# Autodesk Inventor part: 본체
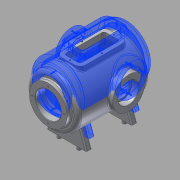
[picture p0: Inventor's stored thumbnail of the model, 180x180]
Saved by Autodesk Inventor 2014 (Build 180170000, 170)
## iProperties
Created: 2016-02
Part Number: 본체
Material: 알루미늄 6061
Document SubType Name: Modeling
Designer: mduedu
Density: 2.71 g/cm^3
Appearance: 알루미늄 - 평지
Mass: 2843.95 g
Surface Area: 2031.13 cm^2
Volume: 1049.43 cm^3
Author: mduedu
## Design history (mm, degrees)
sketch "스케치2"
  geometry: L1 (0, 100)-(0, -100); L2 (65, -75.993)-(65, 100); L3 (65, 100)-(0, 100); A1 r 100 centre (0, 0) between (0, -100) and (65, -75.993); 2 further points
  constraints: 6 end point, 2 midpoint, 2 point on circle, 1 centre point, 1 coincident, 1 horizontal, 1 parallel, 1 vertical
  dimensions: "d3" = 200 distance of L1.start L1.end; "d5" = 130 diameter of L2 L1; "d6" = 100 radius of A1
revolve "회전1" sketch "스케치2" stored, may be unused: angle "d7" = 90 deg
sketch "스케치3"
  geometry: C1 r 47.5 at (0, 0); 1 further point
  constraints: 1 centre point, 1 coincident
  dimensions: "d8" = 95 diameter of C1
extrude "돌출2" join sketch "스케치3" distance "d10" = 10; taper "d11" = 0 deg
sketch "스케치5"
  geometry: L1 (47.5, 110)-(47.5, 100) reference; L2 (47.5, 100)-(65, 100) reference; L3 (65, 100)-(65, -75.993) reference; L4 (-65, -75.993)-(-65, 100) reference; L5 (-65, 100)-(-47.5, 100) reference; L6 (-47.5, 100)-(-47.5, 110) reference; L7 (-47.5, 110)-(47.5, 110) reference; L8 (55, 85)-(55, -71.239); L9 (0, 85)-(55, 85); L10 (0, 85)-(0, -90); A1 r 100 centre (0, 0) between (0, -100) and (65, -75.993) reference; A2 r 100 centre (0, 0) between (-65, -75.993) and (0, -100) reference; A3 r 90 centre (0, 0) between (0, -90) and (55, -71.239); 1 further point
  constraints: 6 end point, 2 point on circle, 1 centre point, 1 parallel, 1 perpendicular, 1 point on line, 1 vertical
  dimensions: "d13" = 10 distance between parallel lines of L3 L8; "d14" = 10 radial gap between concentric circles of A3 A1; "d15" = 15 distance between parallel lines of L9 L2
revolve "회전2" sketch "스케치5" stored, may be unused: angle "d16" = 90 deg
hole "구멍1" diameter "d19" = 65; stored, may be unused: countersink angle "d23" = 90 deg, drill point angle "d25" = 118 deg; dims "d17" = 10, "d18" = 10, "d20" = 6, "d21" = 4, "d22" = 2, "d24" = 8
node "작업 평면1"
sketch "스케치6"
  geometry: L1 (47.5, 110)-(-47.5, 110) reference; C1 r 40 at (0, -17); 1 further point
  constraints: 1 centre point, 1 vertical alignment
  dimensions: "d27" = 80 diameter of C1; "d29" = 127 distance from line of C1.centre L1
extrude "돌출3" join sketch "스케치6" stored distance "d30" = 10; taper "d31" = 0 deg
hole "구멍2" diameter "d34" = 42; stored, may be unused: countersink angle "d38" = 90 deg, drill point angle "d40" = 118 deg; dims "d32" = 10, "d33" = 10, "d35" = 6, "d36" = 52, "d37" = 18, "d39" = 8
sketch "스케치7" dims "d41" = 65
  geometry: C1 r 40 at (0, 0) reference; 3 further points
  constraints: 2 vertical alignment, 1 coincident, 2 other
hole "구멍3" sketch "스케치7" at (0, 32.5) diameter "d43" = 3.242; stored, may be unused: countersink angle "d47" = 90 deg, drill point angle "d49" = 118 deg; dims "d44" = 11, "d45" = 13, "d46" = 18, "d48" = 13
sketch "스케치8" dims "d53" = 80
  geometry: 3 further points
  constraints: 2 vertical alignment, 1 coincident, 2 other
hole "구멍4" sketch "스케치8" at (0, 40) diameter "d56" = 3.242; stored, may be unused: countersink angle "d60" = 90 deg, drill point angle "d62" = 118 deg; dims "d57" = 11, "d58" = 13, "d59" = 18, "d61" = 13
fillet "모깎기1" dims "d66" = 10
fillet "모깎기2" dims "d67" = 3
fillet "모깎기3" dims "d68" = 0.3
chamfer "모따기1" distance "d69" = 1; stored, may be unused: second distance "d70" = 2, angle "d71" = 45 deg
node "작업 평면5"
sketch "스케치10"
  geometry: L1 (-50, -64)-(50, -64); L2 (50, -64)-(50, -50); L3 (50, -50)-(-50, -50); L4 (-50, -50)-(-50, -64); L5 (-50, 0)-(50, 0); L6 (-50, 64)-(50, 64); L7 (50, 64)-(50, 50); L8 (50, 50)-(-50, 50); L9 (-50, 50)-(-50, 64); 2 further points
  constraints: 18 end point, 4 symmetric about line, 2 parallel, 2 perpendicular, 1 coincident, 1 horizontal, 1 midpoint
  dimensions: "d80" = 14 distance of L3.end L1.start; "d82" = 100 distance of L1.start L1.end; "d130" = 50 horizontal distance of L3.end point (0, 0); "d131" = 50 horizontal distance of L3.end point (0, 0); "d132" = 100 distance of L5.start L5.end
extrude "돌출5" join sketch "스케치10" stored distance "d84" = 10; taper "d85" = 0 deg
feature "면 기울기3" dims angle "d135" = 20 deg
sketch "스케치11"
  geometry: L1 (-85, -50)-(-85, 50); L2 (-65, 90)-(-65, -71.239) reference; L3 (-100, -50)-(-41.533, -50) reference; L4 (-100, 50)-(-41.533, 50) reference; 1 further point
  constraints: 2 end point, 2 point on line
  dimensions: "d87" = 20 distance between parallel lines of L1 L2
feature "리브1" sketch "스케치11" dims "d88" = 1, "d89" = 8, "d90" = 0, "d91" = 0, "d92" = 1, "d93" = 1
fillet "모깎기5" dims "d103" = 3
fillet "모깎기6" dims "d105" = 3
node "작업 평면6"
sketch "스케치15"
  geometry: L1 (-30, 60)-(30, 60); L2 (30, 60)-(30, -60); L3 (30, -60)-(-30, -60); L4 (-30, -60)-(-30, 60); 2 further points
  constraints: 8 end point, 2 parallel, 1 horizontal, 1 midpoint, 1 perpendicular, 1 vertical alignment
  dimensions: "d110" = 60 distance of L2.end L3.end; "d112" = 60 distance from line of L3 point (0, 0); "d113" = 120 distance of L1.end L2.end
extrude "돌출8" join sketch "스케치15" stored distance "d114" = 10; taper "d115" = 0 deg
fillet "모깎기7" dims "d116" = 15
sketch "스케치16"
  geometry: L1 (-30, -45)-(-30, 45) reference; L2 (30, 45)-(30, -45) reference; L3 (-15, 60)-(15, 60) reference; L4 (15, -60)-(-15, -60) reference; L5 (-20, -45)-(-20, 45); L6 (-15, 50)-(15, 50); L7 (20, 45)-(20, -45); L8 (15, -50)-(-15, -50); A1 r 15 centre (-15, -45) between (-30, -45) and (-15, -60) reference; A2 r 15 centre (-15, 45) between (-15, 60) and (-30, 45) reference; A3 r 15 centre (15, 45) between (30, 45) and (15, 60) reference; A4 r 15 centre (15, -45) between (15, -60) and (30, -45) reference; A5 r 5 centre (-15, -45) between (-20, -45) and (-15, -50); A6 r 5 centre (-15, 45) between (-15, 50) and (-20, 45); A7 r 5 centre (15, 45) between (20, 45) and (15, 50); A8 r 5 centre (15, -45) between (15, -50) and (20, -45)
  constraints: 8 end point, 8 point on circle, 4 centre point, 7 other
  dimensions: "d137" = 10 distance between parallel lines of L5 L1
extrude "돌출9" cut sketch "스케치16" stored distance "d118" = 10; taper "d119" = 0 deg
fillet "모깎기8" dims "d120" = 3
sketch "스케치17"
  geometry: L1 (-30, -45)-(-30, 45) reference; L2 (30, 45)-(30, -45) reference; L3 (-20, 45)-(-20, -45) reference; L4 (-15, -50)-(15, -50) reference; L5 (20, -45)-(20, 45) reference; L6 (15, 50)-(-15, 50) reference; L7 (-15, 60)-(15, 60) reference; L8 (15, -60)-(-15, -60) reference; L9 (15, 55)-(-15, 55); L10 (-25, 45)-(-25, -45); L11 (-15, -55)-(15, -55); L12 (25, -45)-(25, 45); A1 r 5 centre (-15, 45) between (-15, 50) and (-20, 45) reference; A2 r 5 centre (-15, -45) between (-20, -45) and (-15, -50) reference; A3 r 5 centre (15, -45) between (15, -50) and (20, -45) reference; A4 r 5 centre (15, 45) between (20, 45) and (15, 50) reference; A5 r 15 centre (-15, 45) between (-15, 60) and (-30, 45) reference; A6 r 15 centre (15, 45) between (30, 45) and (15, 60) reference; A7 r 15 centre (15, -45) between (15, -60) and (30, -45) reference; A8 r 15 centre (-15, -45) between (-30, -45) and (-15, -60) reference; A9 r 10 centre (-15, 45) between (-15, 55) and (-25, 45); A10 r 10 centre (-15, -45) between (-25, -45) and (-15, -55); A11 r 10 centre (15, -45) between (15, -55) and (25, -45); A12 r 10 centre (15, 45) between (25, 45) and (15, 55); 4 further points
  constraints: 8 end point, 8 point on circle, 4 centre point, 4 midpoint, 7 other
  dimensions: "d138" = 5 distance between parallel lines of L9 L7
hole "구멍5" sketch "스케치17" at (0, 55), (25, 0), (0, -55), (-25, 0) diameter "d122" = 3.242; stored, may be unused: countersink angle "d126" = 90 deg, drill point angle "d128" = 118 deg; dims "d123" = 9, "d124" = 13, "d125" = 18, "d127" = 11
fillet "모깎기9" dims "d129" = 3
sketch "스케치18"
  geometry: L1 (-46.807, 50)-(46.807, 50) reference; L2 (50, 53)-(50, 61) reference; L3 (46.807, 64)-(-46.807, 64) reference; L4 (-50, 61)-(-50, 53) reference; L5 (-50, 57)-(50, 57); L6 (0, 64)-(0, 50); C1 r 5 at (-25, 57); C2 r 5 at (25, 57); 5 further points; 4 other entities
  constraints: 4 end point, 4 midpoint, 2 centre point, 1 point on line, 1 symmetric about line, 5 other
  dimensions: "d139" = 10 diameter of C1; "d141" = 25 distance from line of L6 C1.centre; "d147" = 57 vertical distance of C2.centre point (0, 0) (derived)
extrude "돌출10" join sketch "스케치18" distance "d142" = 10; taper "d143" = 0 deg
chamfer "모따기2" distance "d144" = 1; stored, may be unused: second distance "d145" = 2, angle "d146" = 45 deg
node "작업 평면7"
fillet "모깎기10" dims "d148" = 0.5
node "솔리드2"
pattern_circular "원형 패턴1" dims angle "d51" = 360 deg
mirror "대칭1"
pattern_circular "원형 패턴2" dims angle "d64" = 360 deg
mirror "대칭2"
node "투영된 루프1"
node "절단 모서리 투영1"
node "절단 모서리 투영2"
node "절단 모서리 투영3"
other parameters: "d26" = 75
